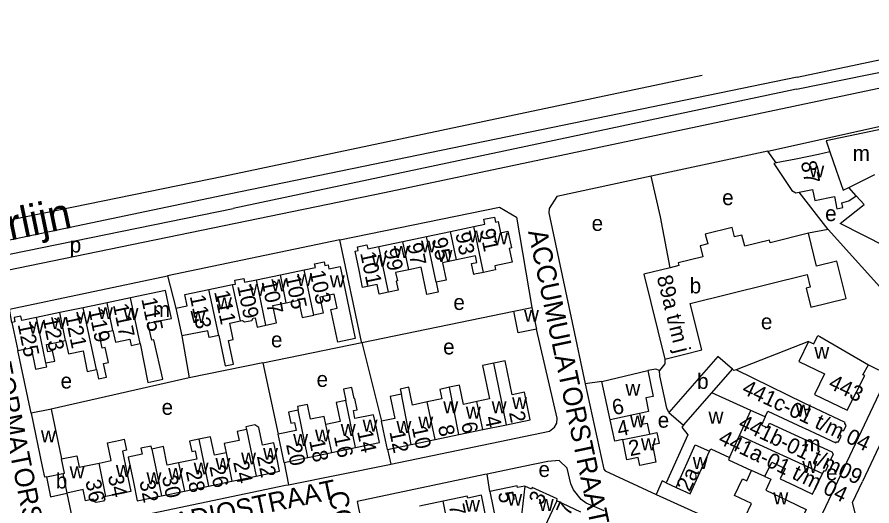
# Model space of a CAD drawing. Extents: x 163026 to 166241, y 382475 to 384501.
# Drawn here: x 163585.6 to 163806.9, y 384011.7 to 384138.3 of the extents above; entities that cross this region are included whole.
import ezdxf

# ---------------------------------------------------------------- set-up
doc = ezdxf.new("R2010")
doc.units = 0
for name, color, linetype in [('BLT_Basislijn', 7, 'Continuous'), ('BLT_Bebouwing', 7, 'Continuous'), ('BLT_Centroide', 7, 'Continuous'), ('BLT_Huisnummer', 7, 'Continuous'), ('BLT_Huisnummer_ tussenligend', 7, 'Continuous'), ('BLT_Huisnummer_reeks', 7, 'Continuous'), ('BLT_Onderverdeling_panden', 7, 'Continuous'), ('BLT_Spoorlijn', 7, 'Continuous'), ('BLT_Straatnaam', 7, 'Continuous'), ('BLT_Waternaam_spoorwegen', 7, 'Continuous')]:
    doc.layers.add(name, color=color, linetype=linetype)

msp = doc.modelspace()

# ---------------------------------------------------------------- linework, layer by layer
at = {"layer": 'BLT_Basislijn'}
for p, q in [((163787.39, 384119.63), (163858.24, 384133.92)), ((163787.39, 384119.63), (163641.5, 384088.72)), ((163779.97, 384103.61), (163749.81, 384097.13)), ((163782.15, 384100.52), (163779.97, 384103.61)), ((163795.65, 384083.33), (163790.51, 384082.33)), ((163813.27, 384063.63), (163795.65, 384083.33)), ((163669.17, 384080.6), (163624.54, 384071.33)), ((163674.81, 384054.03), (163714.17, 384062.15)), ((163729.33, 384059.24), (163732.71, 384043.33)), ((163628.22, 384055.73), (163630.16, 384044.86)), ((163649.22, 384048.73), (163674.81, 384054.03)), ((163674.81, 384054.03), (163679.97, 384033.62)), ((163790.49, 384054.33), (163771.75, 384046.95)), ((163589.21, 384035.74), (163585.75, 384051.96)), ((163649.22, 384048.73), (163630.16, 384044.86)), ((163649.22, 384048.73), (163653.22, 384030.27)), ((163806.07, 384048.22), (163811.17, 384045.74)), ((163811.17, 384045.74), (163788.45, 383997.79)), ((163630.16, 384044.86), (163594.43, 384036.8)), ((163737.04, 384043.94), (163732.71, 384043.33)), ((163681.49, 384026.31), (163682.38, 384022.53)), ((163654.74, 384022.99), (163655.86, 384017.21)), ((163707.27, 384019.94), (163706.74, 384019.82)), ((163708, 384015.49), (163707.27, 384019.94))]:
    msp.add_line(p, q, dxfattribs=at)
for points in [[(163842.68, 384126.99), (163680.68, 384092.81), (163440.33, 384043.29)], [(163779.97, 384103.61), (163827.81, 384114.22), (163833.51, 384115.18)], [(163847.37, 384102.01), (163845.44, 384099.45), (163843.19, 384099.05), (163835.24, 384083.74), (163836.06, 384080.68), (163825.05, 384057.22), (163822.81, 384053.55), (163819.54, 384049.88), (163804.46, 384018.05)], [(163749.81, 384097.13), (163725.37, 384091.88), (163723.4, 384088.69), (163723.29, 384087.59), (163729.33, 384059.24)], [(163754.67, 384073.37), (163752.17, 384086.56), (163749.81, 384097.13)], [(163795.65, 384083.33), (163788.12, 384092.98)], [(163474.67, 384054.48), (163575.47, 384075.23), (163641.5, 384088.72)], [(163669.17, 384080.6), (163710.5, 384089.08), (163714.89, 384086.46), (163718.88, 384063.11)], [(163674.81, 384054.03), (163674.76, 384054.2), (163669.17, 384080.6)], [(163584.25, 384059.18), (163583.57, 384062.68), (163624.54, 384071.33)], [(163624.54, 384071.33), (163626.7, 384062.89)], [(163682.38, 384022.53), (163723.49, 384031.07), (163724.77, 384032.12), (163725.31, 384033.14), (163725.42, 384034.42), (163720.05, 384057.52)], [(163753.29, 384049.73), (163753.31, 384048.49), (163751.95, 384046.78)], [(163751.95, 384046.78), (163751.02, 384047.12), (163748.9, 384046.78)], [(163754.31, 384035.93), (163753.87, 384037.05), (163751.98, 384045.4), (163751.95, 384046.78)], [(163732.71, 384043.33), (163737.51, 384021.21), (163737.9, 384020.78), (163751.09, 384014.71)], [(163737.6, 384010.44), (163732.92, 384012.44), (163731.68, 384013.39), (163729.63, 384015.9), (163728.96, 384017.43), (163728.02, 384021.51), (163725.95, 384023.49), (163722.98, 384023.23), (163716.72, 384021.93), (163707.27, 384019.94)], [(163655.86, 384017.21), (163681.99, 384022.45), (163682.38, 384022.53)], [(163706.74, 384019.82), (163673.68, 384012.84), (163680.12, 383981.15)], [(163598.48, 384015.01), (163600.45, 384005.61), (163655.1, 384017.06), (163655.86, 384017.21)], [(163753.66, 384017.71), (163752.6, 384018.2), (163751.09, 384014.71)], [(163798.85, 384000.4), (163802.93, 384008.56), (163801.91, 384012.64), (163804.46, 384018.05)], [(163751.09, 384014.71), (163788.45, 383997.79)]]:
    msp.add_lwpolyline(points, dxfattribs=at)
at = {"layer": 'BLT_Bebouwing'}
for p, q in [((163796.06, 384103.37), (163793.13, 384102.74)), ((163793.13, 384102.74), (163787.26, 384101.55)), ((163697.8, 384082.79), (163703.88, 384084.06)), ((163685.45, 384080.22), (163691.63, 384081.51)), ((163691.63, 384081.51), (163697.8, 384082.79)), ((163679.27, 384078.93), (163685.45, 384080.22)), ((163653.76, 384071.59), (163659.95, 384072.88)), ((163754.67, 384073.37), (163747.88, 384071.69)), ((163647.58, 384070.3), (163653.76, 384071.59)), ((163747.88, 384071.69), (163753.29, 384049.73)), ((163635.21, 384067.73), (163641.39, 384069.02)), ((163614.96, 384065.58), (163608.87, 384064.31)), ((163608.87, 384064.31), (163602.68, 384063.02)), ((163596.62, 384061.76), (163590.59, 384060.5)), ((163602.68, 384063.02), (163596.62, 384061.76)), ((163626.7, 384062.89), (163628.22, 384055.73)), ((163714.17, 384062.15), (163718.88, 384063.11)), ((163718.88, 384063.11), (163720.05, 384057.52)), ((163584.25, 384059.18), (163585.75, 384051.96)), ((163634.95, 384057.03), (163628.22, 384055.73)), ((163791.89, 384053.66), (163792.95, 384055.88)), ((163792.95, 384055.88), (163793.49, 384055.62)), ((163793.49, 384055.62), (163806.07, 384048.22)), ((163790.49, 384054.33), (163791.89, 384053.66)), ((163737.04, 384043.94), (163748.9, 384046.78)), ((163739.18, 384033.99), (163737.04, 384043.94)), ((163594.43, 384036.8), (163597.1, 384023.89)), ((163589.21, 384035.74), (163592.09, 384021.9)), ((163754.31, 384035.93), (163758.11, 384032.6)), ((163706.15, 384031.46), (163712.31, 384032.74)), ((163693.82, 384028.88), (163699.98, 384030.17)), ((163699.98, 384030.17), (163706.15, 384031.46)), ((163687.66, 384027.6), (163693.82, 384028.88)), ((163667.07, 384025.57), (163673.23, 384026.85)), ((163681.49, 384026.31), (163687.66, 384027.6)), ((163654.74, 384022.99), (163660.91, 384024.28)), ((163660.91, 384024.28), (163667.07, 384025.57)), ((163592.09, 384021.9), (163592.66, 384019.13)), ((163779.24, 384019.34), (163781.03, 384023.08)), ((163593.16, 384019.24), (163592.66, 384019.13)), ((163641.22, 384018.12), (163647.48, 384019.43)), ((163779.24, 384019.34), (163780.77, 384018.68)), ((163628.94, 384015.55), (163635.18, 384016.86)), ((163635.18, 384016.86), (163641.22, 384018.12)), ((163623.01, 384014.32), (163628.94, 384015.55)), ((163708, 384015.49), (163709.85, 384006.58)), ((163695.9, 384012.95), (163689.78, 384011.67)), ((163731.6, 384010.13), (163725.34, 384013.02))]:
    msp.add_line(p, q, dxfattribs=at)
for points in [[(163824.22, 384109.32), (163823.61, 384112.25), (163795.05, 384106.22), (163796.06, 384103.37)], [(163787.26, 384101.55), (163782.15, 384100.52)], [(163782.15, 384100.52), (163781.51, 384100.39), (163786.19, 384093.38), (163787.22, 384092.8), (163788.12, 384092.98)], [(163788.12, 384092.98), (163791.59, 384093.68), (163792.17, 384090.83), (163797.25, 384091.85)], [(163797.25, 384091.85), (163797.88, 384088.65), (163799.4, 384088.96), (163799.14, 384090.21), (163800.99, 384090.69), (163802.84, 384092.04)], [(163810.65, 384078.82), (163798.71, 384084.88), (163804.89, 384089.78), (163802.84, 384092.04)], [(163703.88, 384084.06), (163706.74, 384084.65), (163706.46, 384085.94), (163709.18, 384086.52), (163709.46, 384085.22), (163710.15, 384085.36), (163710.76, 384082.46), (163712.68, 384082.86), (163713.58, 384078.53), (163712.99, 384078.41), (163713.75, 384074.8), (163709.27, 384073.86), (163709.49, 384072.83), (163706.36, 384072.17)], [(163790.51, 384082.33), (163780.58, 384079.88), (163780.41, 384080.55), (163774, 384078.97), (163773.29, 384081.85), (163771.35, 384081.37), (163770.76, 384083.77), (163763.8, 384082.05), (163764.42, 384079.57), (163762.43, 384079.08), (163763.14, 384076.2), (163756.77, 384074.63), (163756.94, 384073.93), (163754.67, 384073.37)], [(163753.29, 384049.73), (163758.15, 384050.93), (163762.88, 384052.1), (163759.9, 384064.16), (163790.15, 384071.62), (163790.95, 384068.36), (163789.9, 384068.1), (163791.12, 384063.15), (163800.27, 384065.4), (163799.08, 384070.22), (163797.88, 384075.07), (163792.62, 384073.77), (163790.51, 384082.33)], [(163681.75, 384067.06), (163679.35, 384066.56), (163678.83, 384069.05), (163675.05, 384068.26), (163674.12, 384072.75), (163673.1, 384077.65), (163673.94, 384077.82), (163673.74, 384078.79), (163676.16, 384079.3), (163676.37, 384078.33), (163679.27, 384078.93)], [(163659.95, 384072.88), (163662.82, 384073.48), (163662.62, 384074.44), (163665.06, 384074.95), (163665.26, 384073.99), (163666.13, 384074.17), (163666.34, 384073.14), (163669.27, 384073.75), (163670.55, 384067.61), (163673.16, 384055.04), (163668.6, 384054.08), (163666.8, 384062.61), (163668.44, 384062.95), (163667.69, 384066.55), (163663.94, 384065.77), (163664.8, 384061.62), (163662.4, 384061.12)], [(163699.33, 384075.45), (163695.75, 384074.7), (163696.69, 384070.16), (163694.12, 384069.62)], [(163706.36, 384072.17), (163704.06, 384071.69), (163703.84, 384071.65), (163703.25, 384074.48), (163704.63, 384074.77), (163704.28, 384076.47), (163699.33, 384075.45)], [(163686.98, 384072.88), (163683.61, 384072.18), (163684.06, 384070.02), (163683.72, 384069.95), (163684.22, 384067.57), (163681.75, 384067.06)], [(163694.12, 384069.62), (163694.64, 384067.09), (163691.66, 384066.47), (163690.18, 384073.55), (163686.98, 384072.88)], [(163641.39, 384069.02), (163642.13, 384069.17), (163641.93, 384070.14), (163644.29, 384070.63), (163644.49, 384069.66), (163647.58, 384070.3)], [(163626.7, 384062.89), (163629.64, 384063.5), (163629.03, 384066.44), (163635.21, 384067.73)], [(163617.42, 384053.77), (163619.46, 384043.7), (163623.36, 384044.51), (163620.99, 384054.75), (163620.46, 384054.63), (163619.45, 384059), (163622.83, 384059.7), (163625.54, 384060.26), (163625.06, 384062.57), (163624.04, 384067.47), (163614.96, 384065.58)], [(163650.03, 384058.51), (163652.78, 384059.09), (163651.84, 384063.62), (163655.27, 384064.33)], [(163655.27, 384064.33), (163658.49, 384065), (163659.43, 384060.5), (163662.4, 384061.12)], [(163720.05, 384057.52), (163715.31, 384056.55), (163714.17, 384062.15)], [(163590.59, 384060.5), (163586.79, 384059.71), (163586.55, 384060.86), (163584.79, 384060.49), (163585.03, 384059.35), (163584.25, 384059.18)], [(163637.79, 384055.81), (163639.42, 384047.98), (163641.6, 384048.43), (163640.33, 384054.54), (163641.57, 384054.8), (163640.67, 384059.08), (163643.39, 384059.65)], [(163643.39, 384059.65), (163643.93, 384059.76), (163644.48, 384059.37), (163646.34, 384059.71), (163646.74, 384060.35), (163647.24, 384060.45), (163647.75, 384058.04), (163650.03, 384058.51)], [(163606.12, 384047.06), (163606.63, 384044.6), (163608.72, 384045.03), (163607.97, 384048.62), (163609.21, 384048.88), (163608.41, 384052.7), (163607.61, 384052.53), (163606.8, 384056.42), (163610.36, 384057.16)], [(163610.36, 384057.16), (163611.06, 384054.1), (163614.75, 384054.93), (163615.09, 384053.29), (163617.42, 384053.77)], [(163637.79, 384055.81), (163635.28, 384055.29), (163634.95, 384057.03)], [(163593.04, 384048.76), (163595.34, 384049.24), (163594.79, 384051.91), (163593.55, 384051.65), (163593.17, 384053.48), (163598.13, 384054.51)], [(163598.13, 384054.51), (163598.89, 384051.06), (163602.65, 384051.84), (163603.74, 384046.56), (163606.12, 384047.06)], [(163585.75, 384051.96), (163589.18, 384052.68), (163590.34, 384047.16), (163593.25, 384047.77), (163593.04, 384048.76)], [(163790.49, 384054.33), (163787.99, 384049.09), (163794.64, 384045.92), (163792.1, 384040.57), (163800.55, 384036.55), (163805.08, 384045.47), (163804.63, 384045.68), (163806.07, 384048.22)], [(163770.81, 384047.1), (163767.02, 384050.43), (163754.31, 384035.93)], [(163709.04, 384048.65), (163706.12, 384048.04), (163707.93, 384039.41), (163704.63, 384038.72)], [(163712.31, 384032.74), (163718.47, 384034.03), (163716.98, 384041.19), (163713.76, 384040.51), (163711.93, 384049.26), (163709.04, 384048.65)], [(163748.9, 384046.78), (163750.27, 384040.07), (163748.37, 384039.68)], [(163771.75, 384046.95), (163771.15, 384046.8), (163770.81, 384047.1)], [(163789.46, 384031.85), (163797.61, 384028.01), (163797.73, 384028.27), (163798.31, 384028.31), (163798.99, 384029.74), (163798.62, 384030.27), (163799.08, 384031.23), (163799.71, 384031.28), (163800.29, 384032.51), (163799.93, 384033.04), (163800.05, 384033.28), (163789.43, 384038.35), (163771.75, 384046.95)], [(163673.23, 384026.85), (163679.4, 384028.14), (163678.38, 384033.03), (163677.86, 384035.34), (163673.08, 384034.34), (163672.65, 384036.4), (163673.65, 384036.61), (163673.04, 384039.54), (163672.88, 384039.51), (163672.28, 384042.35), (163670.09, 384041.91), (163670.69, 384039.05)], [(163691.78, 384038.63), (163687.99, 384037.84), (163687.48, 384040.32), (163687.04, 384042.43), (163684.81, 384041.97), (163685.08, 384040.65)], [(163697.57, 384042.43), (163695.01, 384041.9), (163695.53, 384039.42), (163691.78, 384038.63)], [(163704.63, 384038.72), (163701.14, 384037.99), (163700.1, 384042.96), (163697.57, 384042.43)], [(163670.69, 384039.05), (163668.22, 384038.53), (163668.83, 384035.62), (163669.28, 384033.57), (163665.56, 384032.79)], [(163685.08, 384040.65), (163682.23, 384040.06), (163683.43, 384034.34), (163679.97, 384033.62)], [(163748.37, 384039.68), (163749.09, 384036.14), (163746.75, 384035.67)], [(163594.43, 384036.8), (163594.03, 384036.72), (163589.21, 384035.74)], [(163665.56, 384032.79), (163665.56, 384032.79), (163665.12, 384034.89), (163661.56, 384034.14), (163660.75, 384038.01), (163658.15, 384037.46), (163658.36, 384036.47)], [(163658.36, 384036.47), (163655.88, 384035.95), (163656.47, 384033.12), (163657.43, 384033.33), (163657.87, 384031.24), (163653.22, 384030.27)], [(163746.75, 384035.67), (163747.33, 384032.87), (163748.76, 384033.17), (163749.34, 384030.3)], [(163779.3, 384034.78), (163778.35, 384032.66), (163779.89, 384031.98), (163780.4, 384033.11), (163796.56, 384025.71)], [(163779.3, 384034.78), (163779.97, 384036.24), (163789.03, 384032.05), (163789.46, 384031.85)], [(163649.1, 384027.47), (163648.14, 384032.06), (163647.15, 384032.68), (163644.81, 384032.19), (163644.96, 384031.49)], [(163681.49, 384026.31), (163680.47, 384031.2), (163679.97, 384033.62)], [(163742.43, 384028.89), (163740.37, 384028.47), (163739.18, 384033.99)], [(163758.11, 384032.6), (163757.68, 384032.1), (163759.31, 384030.1), (163753.66, 384017.71)], [(163644.96, 384031.49), (163642.58, 384030.99), (163643.07, 384028.68), (163639.19, 384027.87), (163639.69, 384025.47)], [(163654.74, 384022.99), (163653.72, 384027.89), (163653.22, 384030.27)], [(163749.34, 384030.3), (163751.25, 384030.69), (163751.82, 384027.88), (163750.11, 384027.53), (163751.02, 384023.07), (163746.81, 384022.21), (163746.4, 384024.23), (163743.51, 384023.64), (163742.43, 384028.89)], [(163606.8, 384022.82), (163609.94, 384023.47), (163608.99, 384028.07), (163612.26, 384028.74), (163613.34, 384028.97), (163613.93, 384026.11), (163612.85, 384025.88), (163613.99, 384020.38), (163615, 384015.48), (163608.6, 384014.16)], [(163632.64, 384028.99), (163630.26, 384028.49), (163630.81, 384025.84), (163631.68, 384026.02), (163632.13, 384023.86), (163627.41, 384022.88)], [(163639.69, 384025.47), (163636.67, 384024.84), (163635.67, 384029.62), (163632.64, 384028.99)], [(163647.48, 384019.43), (163653.57, 384020.7), (163652.55, 384025.59), (163652.03, 384028.08), (163649.1, 384027.47)], [(163620.48, 384026.45), (163620.32, 384027.22), (163617.64, 384026.66), (163617.96, 384025.1), (163614.33, 384024.34), (163615.68, 384017.89), (163616.7, 384013), (163623.01, 384014.32)], [(163627.41, 384022.88), (163624.47, 384022.26), (163623.47, 384027.07), (163620.48, 384026.45)], [(163756.21, 384016.52), (163759.87, 384014.83), (163764.89, 384025.86)], [(163764.89, 384025.86), (163765.19, 384026.51)], [(163765.19, 384026.51), (163770.07, 384024.28)], [(163796.56, 384025.71), (163796.9, 384025.08), (163796.24, 384023.68), (163795.61, 384023.46), (163795.21, 384022.62), (163795.56, 384022.11), (163794.91, 384020.74), (163794.42, 384020.7), (163794.15, 384020.14)], [(163597.1, 384023.89), (163601.03, 384024.7), (163601.62, 384021.74), (163606.8, 384022.82)], [(163770.07, 384024.28), (163769.78, 384023.66), (163775.79, 384020.92)], [(163781.03, 384023.08), (163784.49, 384021.43), (163783.2, 384018.72), (163787.06, 384016.88), (163791.57, 384014.73), (163794.15, 384020.14)], [(163593.16, 384019.24), (163594.23, 384014.08), (163598.48, 384015.01)], [(163780.77, 384018.68), (163779.44, 384015.79), (163785.05, 384013.13), (163789.93, 384010.81), (163786.33, 384003.24), (163781.27, 384005.65), (163781.01, 384005.09), (163780.59, 384004.95), (163778.06, 384006.15), (163777.78, 384006.55), (163778.01, 384007.02), (163774.14, 384008.86), (163775.77, 384012.31), (163771.35, 384014.41), (163773.41, 384018.75), (163774.51, 384018.23), (163775.79, 384020.92)], [(163717.02, 384016.85), (163715.15, 384016.47), (163715.05, 384016.94), (163708, 384015.49)], [(163725.34, 384013.02), (163725.46, 384013.52), (163718.98, 384016.5), (163718.77, 384016.05), (163717.02, 384016.85)], [(163753.66, 384017.71), (163756.21, 384016.52)], [(163608.6, 384014.16), (163608.16, 384014.06), (163608.29, 384013.45), (163607.98, 384012.95), (163606.08, 384012.56), (163605.44, 384012.86), (163605.31, 384013.48), (163603.3, 384013.06), (163602.7, 384015.94), (163598.48, 384015.01)], [(163701.38, 383996.92), (163702.17, 383998.45), (163700.86, 384004.72), (163703.74, 384005.32), (163703.17, 384008.08), (163707, 384008.88), (163705.83, 384014.51), (163702.26, 384013.73), (163702.17, 384014.26), (163695.9, 384012.95)]]:
    msp.add_lwpolyline(points, dxfattribs=at)
at = {"layer": 'BLT_Onderverdeling_panden'}
for p, q in [((163800.93, 384094.15), (163807.68, 384097.56)), ((163802.84, 384092.04), (163800.93, 384094.15)), ((163706.36, 384072.17), (163703.88, 384084.06)), ((163694.12, 384069.62), (163691.63, 384081.51)), ((163699.33, 384075.45), (163697.8, 384082.79)), ((163681.75, 384067.06), (163679.27, 384078.93)), ((163686.98, 384072.88), (163685.45, 384080.22)), ((163662.4, 384061.12), (163659.95, 384072.88)), ((163650.03, 384058.51), (163647.58, 384070.3)), ((163655.27, 384064.33), (163653.76, 384071.59)), ((163637.79, 384055.81), (163635.21, 384067.73)), ((163643.39, 384059.65), (163641.39, 384069.02)), ((163617.42, 384053.77), (163614.96, 384065.58)), ((163610.36, 384057.16), (163608.87, 384064.31)), ((163598.13, 384054.51), (163596.62, 384061.76)), ((163606.12, 384047.06), (163602.68, 384063.02)), ((163593.04, 384048.76), (163590.59, 384060.5)), ((163712.31, 384032.74), (163709.04, 384048.65)), ((163765.45, 384040.98), (163770.81, 384047.1)), ((163699.98, 384030.17), (163697.57, 384042.43)), ((163673.23, 384026.85), (163670.69, 384039.05)), ((163687.66, 384027.6), (163685.08, 384040.65)), ((163758.11, 384032.6), (163765.45, 384040.98)), ((163775.62, 384036.43), (163765.45, 384040.98)), ((163693.82, 384028.88), (163691.78, 384038.63)), ((163706.15, 384031.46), (163704.63, 384038.72)), ((163660.91, 384024.28), (163658.36, 384036.47)), ((163746.75, 384035.67), (163739.18, 384033.99)), ((163772.67, 384029.99), (163775.62, 384036.43)), ((163779.3, 384034.78), (163775.62, 384036.43)), ((163667.07, 384025.57), (163665.56, 384032.79)), ((163644.96, 384031.49), (163647.48, 384019.43)), ((163742.43, 384028.89), (163749.34, 384030.3)), ((163632.64, 384028.99), (163635.18, 384016.86)), ((163772.67, 384029.99), (163794.15, 384020.14)), ((163620.48, 384026.45), (163623.01, 384014.32)), ((163639.69, 384025.47), (163641.22, 384018.12)), ((163608.6, 384014.16), (163606.8, 384022.82)), ((163627.41, 384022.88), (163628.94, 384015.55)), ((163597.41, 384020.13), (163598.48, 384015.01)), ((163779.24, 384019.34), (163775.79, 384020.92)), ((163717.02, 384016.85), (163716, 384007.86)), ((163699.33, 383996.52), (163695.9, 384012.95)), ((163725.34, 384013.02), (163721.67, 384005.2))]:
    msp.add_line(p, q, dxfattribs=at)
for points in [[(163796.06, 384103.37), (163797.71, 384098.66), (163799.53, 384093.44)], [(163799.53, 384093.44), (163800.93, 384094.15)], [(163770.07, 384024.28), (163772.67, 384029.99)], [(163756.21, 384016.52), (163761.15, 384027.57), (163764.89, 384025.86)], [(163597.41, 384020.13), (163597.86, 384020.22), (163597.1, 384023.89)], [(163593.16, 384019.24), (163597.41, 384020.13)]]:
    msp.add_lwpolyline(points, dxfattribs=at)
at = {"layer": 'BLT_Spoorlijn'}
for points in [[(163787.6, 384122.75), (163857.5, 384137.48), (163861.35, 384138.3)], [(163762.94, 384123.21), (163639.01, 384097.02)], [(163787.6, 384122.75), (163640.46, 384092.45)], [(163639.01, 384097.02), (163471.35, 384062.78)], [(163640.46, 384092.45), (163471.97, 384057.17)]]:
    msp.add_lwpolyline(points, dxfattribs=at)

# ---------------------------------------------------------------- texts
at = {"layer": 'BLT_Centroide'}
for s, p in [('m', (163801.97, 384101.05)), ('w', (163790.73, 384096.78)), ('e', (163768.17, 384089.61)), ('e', (163794.83, 384085.47)), ('e', (163734.36, 384082.93)), ('w', (163702.52, 384079.94)), ('w', (163708.86, 384079.44)), ('p', (163599.22, 384077.33)), ('w', (163683.12, 384075.92)), ('w', (163690.17, 384077.36)), ('w', (163677.42, 384073.66)), ('w', (163694.42, 384074.89)), ('w', (163651.42, 384067.31)), ('w', (163658.08, 384068.7)), ('w', (163666.55, 384068.33)), ('b', (163759.75, 384066.75)), ('w', (163645.72, 384066.11)), ('w', (163637.32, 384062.62)), ('e', (163698.55, 384062.46)), ('m', (163620.73, 384060.62)), ('w', (163600.88, 384058.88)), ('w', (163606.52, 384060.08)), ('w', (163613.14, 384059.88)), ('w', (163630.49, 384059.09)), ('w', (163716.85, 384059.41)), ('w', (163588.64, 384056.33)), ('w', (163594.36, 384057.5)), ('e', (163778.19, 384057.45)), ('e', (163651.33, 384052.78)), ('e', (163695.91, 384050.94)), ('w', (163792.03, 384049.83)), ('e', (163663.13, 384042.54)), ('b', (163761.67, 384042.02)), ('e', (163596.84, 384042.12)), ('w', (163743.11, 384040.23)), ('w', (163713.75, 384036.78)), ('e', (163623, 384035.31)), ('w', (163695.94, 384035.7)), ('w', (163701.78, 384034.33)), ('w', (163708.47, 384035.73)), ('w', (163787.27, 384034.85)), ('w', (163689.47, 384031.78)), ('w', (163744.31, 384032.03)), ('e', (163751.47, 384031.97)), ('w', (163764.62, 384033.02)), ('w', (163669.39, 384029.83)), ('w', (163675.05, 384030.98)), ('w', (163683.81, 384030.61)), ('w', (163657.06, 384027.27)), ('w', (163662.72, 384028.42)), ('w', (163747.14, 384026.12)), ('m', (163789.18, 384025.88)), ('w', (163649.27, 384023.66)), ('w', (163636.94, 384021.06)), ('w', (163643.58, 384022.45)), ('w', (163760.55, 384021.28)), ('w', (163599.19, 384018.86)), ('w', (163611.17, 384019.2)), ('w', (163624.7, 384018.48)), ('w', (163631.3, 384019.86)), ('e', (163720.6, 384019.21)), ('w', (163788.92, 384020.25)), ('e', (163795.05, 384018.34)), ('b', (163595.6, 384016.23)), ('w', (163619.09, 384017.31)), ('w', (163712.52, 384011.77)), ('w', (163781.41, 384012.12)), ('w', (163701.59, 384010.2)), ('w', (163720.67, 384010.42))]:
    msp.add_text(s, height=4, dxfattribs=at).set_placement(p)
msp.add_text('w', height=4, rotation=359, dxfattribs=at).set_placement((163591.72, 384028.19))
at = {"layer": 'BLT_Huisnummer'}
for s, rotation, p in [('87', 281.398, (163788.49, 384100.71)), ('91', 281.7587, (163705.34, 384083.13)), ('95', 281.7611, (163692.92, 384080.82)), ('101', 281.7594, (163674.4, 384077.21)), ('103', 281.7636, (163661.3, 384072.37)), ('107', 281.7588, (163648.86, 384069.83)), ('115', 281.7509, (163617.74, 384065.3)), ('113', 281.7594, (163630.27, 384066.01)), ('119', 281.7648, (163604.06, 384062.49)), ('125', 281.761, (163585.7, 384058.73)), ('443', 334.5152, (163795.41, 384042.34)), ('6', 11.5656, (163740.1, 384035.17)), ('2', 281.7949, (163712.93, 384035.88)), ('6', 281.7945, (163700.55, 384033.09)), ('14', 281.8031, (163673.61, 384031)), ('10', 281.7931, (163687.78, 384032)), ('18', 281.8043, (163661.19, 384028.6)), ('2', 11.5482, (163744.34, 384024.58)), ('22', 281.807, (163647.64, 384024.6)), ('26', 281.8011, (163635.35, 384021.95)), ('2a', 65.3425, (163759.73, 384015.15)), ('30', 281.7931, (163623.04, 384019.27)), ('36', 281.6829, (163603.23, 384018.19)), ('5', 281.1844, (163710.07, 384015.09)), ('3', 64.8869, (163721.49, 384011.67)), ('7', 281.8063, (163697.35, 384011.84)), ('7', 66.2025, (163728.64, 384008.88))]:
    msp.add_text(s, height=4, rotation=rotation, dxfattribs=at).set_placement(p)
at = {"layer": 'BLT_Huisnummer_ tussenligend'}
for s, rotation, p in [('93', 281.7587, (163699.04, 384082.21)), ('97', 281.7611, (163686.51, 384079.47)), ('99', 281.7611, (163680.5, 384078.11)), ('105', 281.7636, (163654.99, 384071.1)), ('109', 281.7588, (163642.55, 384068.66)), ('111', 281.7588, (163636.59, 384067.15)), ('117', 281.7509, (163610.37, 384063.76)), ('121', 281.7648, (163597.98, 384060.97)), ('123', 281.7648, (163592.17, 384060.24)), ('4', 281.7949, (163706.62, 384034.63)), ('8', 281.7945, (163694.54, 384032.3)), ('4', 11.5482, (163741.38, 384029.63)), ('12', 281.7931, (163681.96, 384030.92)), ('20', 281.8043, (163655.21, 384027.62)), ('16', 281.8031, (163667.59, 384029.74)), ('24', 281.807, (163641.52, 384023.06)), ('34', 281.7931, (163609.07, 384019.47)), ('28', 281.8011, (163629.24, 384020.68)), ('32', 281.7931, (163617.22, 384018.09))]:
    msp.add_text(s, height=4, rotation=rotation, dxfattribs=at).set_placement(p)
at = {"layer": 'BLT_Huisnummer_reeks'}
for s, rotation, p in [('89a t/m j', 283.8556, (163751.2, 384070.96)), ('441c-01 t/m 04', 334.7737, (163773.02, 384040.97)), ('441b-01 t/m09', 334.5141, (163772.09, 384031.96)), ('441a-01 t/m 04', 334.5165, (163766.9, 384028.02))]:
    msp.add_text(s, height=4, rotation=rotation, dxfattribs=at).set_placement(p)
at = {"layer": 'BLT_Straatnaam'}
for s, height, rotation, p in [('ACCUMULATORSTRAAT', 5, 282.0028, (163717.87, 384082.77)), ('TRANSFORMATORSTRAAT', 4.9999, 281.3104, (163574.58, 384071)), ('RADIOSTRAAT', 5, 11.9534, (163622.06, 384003.87)), ('CONDENSATORSTRAAT', 5, 281.6774, (163666.1, 384015.07))]:
    msp.add_text(s, height=height, rotation=rotation, dxfattribs=at).set_placement(p)
at = {"layer": 'BLT_Waternaam_spoorwegen'}
msp.add_text('Spoorlijn', height=8, rotation=11.806, dxfattribs=at).set_placement((163559.38, 384075.31))

doc.saveas('drawing.dxf')
